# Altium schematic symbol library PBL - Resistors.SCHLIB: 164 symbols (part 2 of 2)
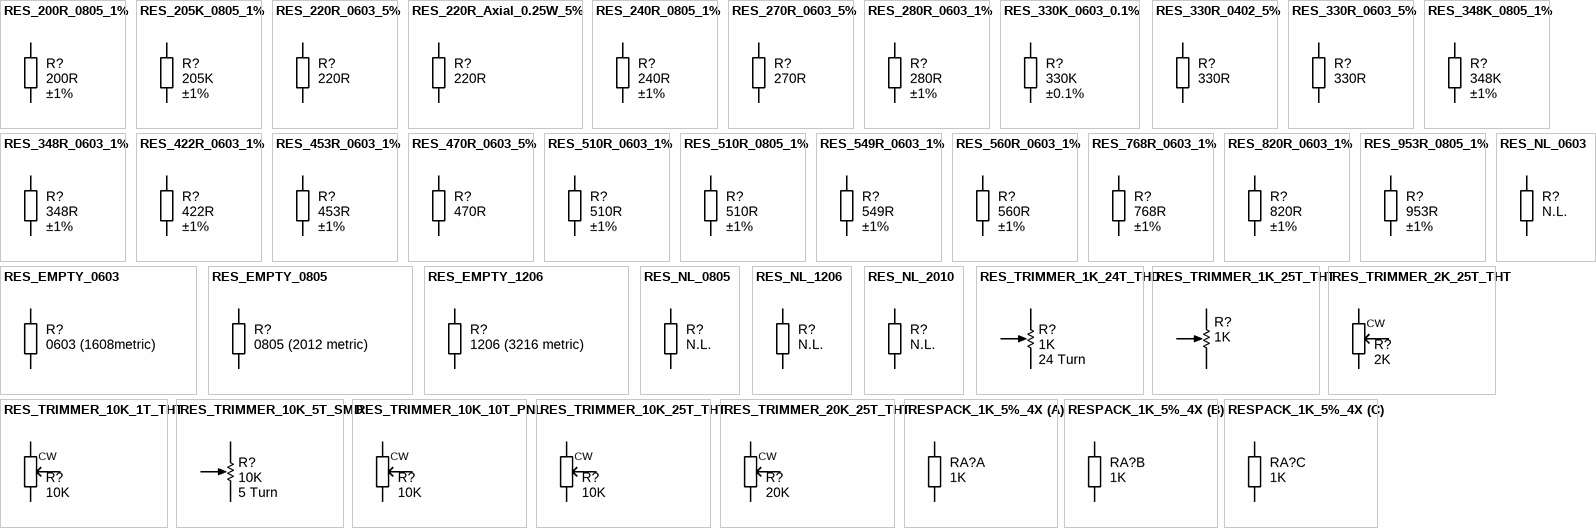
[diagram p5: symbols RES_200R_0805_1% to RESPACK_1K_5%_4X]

## RES_TRIMMER_10K_1T_THT
designator R?, comment value 10K  (hidden comment: Single-turn pot)
Trimmer THD 10K 200mW Single-turn; Manufacturer 1: Bourns Inc.; Manufacturer Part Number 1: 3306F-1-103; Tolerance: ±25%; Ratings: 1/5W; SCDType: spec
footprint POT_3306F
pins: CCW 1, CW 3, W 2

## RES_TRIMMER_10K_5T_SMD
designator R?, comment 5 Turn  value 10K
Trimmer SMD 10K 250mW 5-turn Side-adjust; Manufacturer 1: Bourns Inc.; Manufacturer Part Number 1: 3214G-1-103E; Tolerance: 10%; Ratings: 5 turn variable cermet; Number of Turns: 5; SCDType: spec
footprint TrimPot_SMD_Bourns_3214G (Bourns- 3214G - TRIMMER)
pins: 1 CCW, 2 WIPER, 3 CW

## RES_TRIMMER_10K_10T_PNL
designator R?, comment value 10K  (hidden comment: 10 turns)  (mechanical)
Trimmer panel mount 10K 2W 10-turn; Manufacturer: Bourns Inc.; Manufacturer Part Number: 3590S-2-103L; Tolerance: ±5%; Ratings: 2W; ±50ppm/°C; SCDType: spec
pins: 1 CCW, 2 W, 3 CW

## RES_TRIMMER_10K_25T_THT
designator R?, comment value 10K  (hidden comment: 25 turns)
Trimmer THD 10K 500mW 25-turn; Manufacturer 1: Murata Electronics North America; Manufacturer Part Number 1: PV36X103C01B00; Tolerance: ±10%; Ratings: 1/2W; ±100ppm/°C; SCDType: spec
footprint TRIMPOT_THT_PV36X (TRIMMER, MURATA, PV36X)
pins: CCW 1, CW 3, W 2

## RES_TRIMMER_20K_25T_THT
designator R?, comment value 20K  (hidden comment: 25 turns)
Trimmer THD 20K 500mW 25-turn; Manufacturer 1: Murata Electronics North America; Manufacturer Part Number 1: PV36X203C01B00; Tolerance: ±10%; Ratings: 1/2W; ±100ppm/°C; SCDType: spec
footprint TrimPot_THT_PV36X (TRIMMER, MURATA, PV36X)
pins: CCW 1, CW 3, W 2

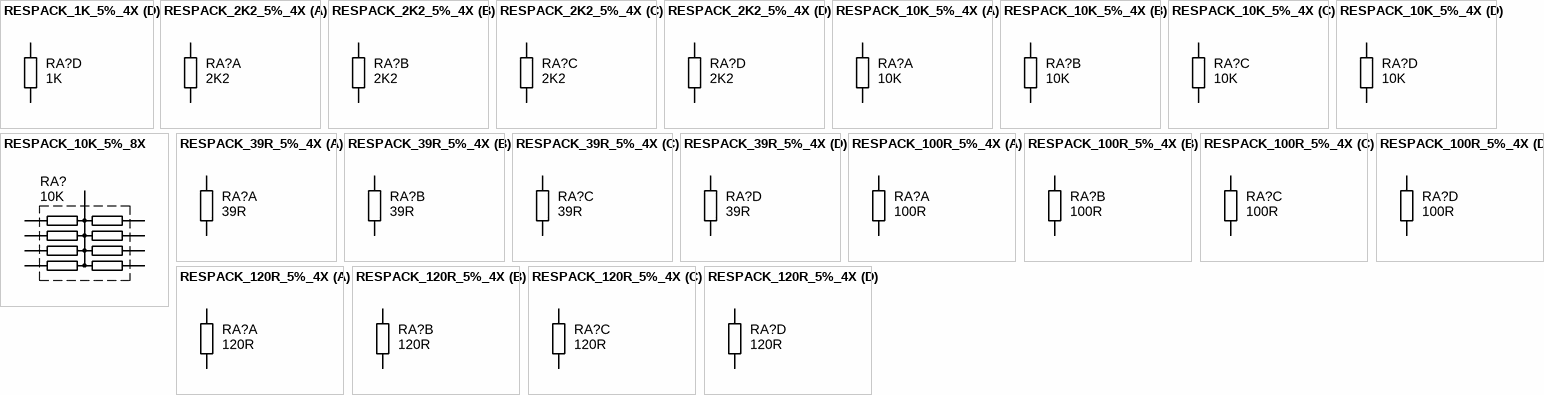
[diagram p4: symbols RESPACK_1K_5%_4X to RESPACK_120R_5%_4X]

## RESPACK_1K_5%_4X
designator RA?, comment value 1K  (hidden comment: Film Res Pack)
Resistor array 1K Ohm 4-pack 62.5mW 5% 4x1608 SMD; Manufacturer 1: Yageo; Manufacturer Part Number 1: YC164-JR-071KL; Ratings: 1/16 W; Number of Resistors: 4; Circuit Type: Isolated; SCDType: source
footprint RESCAXS50P160X320X70-8N (Resistor Pack, Body 1.6x3.2mm, 4x0603, IPC Medium Density)
part A pins: 1, 8
part B pins: 2, 7
part C pins: 3, 6
part D pins: 4, 5

## RESPACK_2K2_5%_4X
designator RA?, comment value 2K2  (hidden comment: Thick Film)
Resistor array 2.2K Ohm 4-pack 62.5mW 5% 4x1608 SMD; Manufacturer 1: Yageo; Manufacturer Part Number 1: YC164-JR-072K2L; Ratings: 1/16 W; Number of Resistors: 4; Circuit Type: Isolated; SCDType: source
footprint RESCAXS50P160X320X70-8N (Resistor Pack, Body 1.6x3.2mm, 4x0603, IPC Medium Density)
part A pins: 1, 8
part B pins: 2, 7
part C pins: 3, 6
part D pins: 4, 5

## RESPACK_10K_5%_4X
designator RA?, comment value 10K  (hidden comment: Film Res Cap)
Resistor array 10K Ohm 4-pack 62.5mW 5% 4x1608 SMD; Manufacturer 1: Yageo; Manufacturer Part Number 1: YC164-JR-0710KL; Ratings: 1/16 W; Number of Resistors: 4; Circuit Type: Isolated; SCDType: source
footprint RESCAXS50P160X320X70-8N (Resistor Pack, Body 1.6x3.2mm, 4x0603, IPC Medium Density)
part A pins: 1, 8
part B pins: 2, 7
part C pins: 3, 6
part D pins: 4, 5

## RESPACK_10K_5%_8X
designator RA?, comment value 10K  (hidden comment: Thick Film)
Resistor array 10K Ohm 8-pack 62.5mW 5% 1608 SMD; Manufacturer 1: Panasonic - ECG; Manufacturer Part Number 1: EXB-E10C103J; Ratings: 1/16 W; Number of Resistors: 8; SCDType: source
footprint RESP4021N8X (Resistor Pack, Body 4.0x2.1mm, 8 elements bussed, IPC Medium Density)
pins: 1 COM, 2, 3, 4, 5, 6 COM, 7, 8, 9, 10

## RESPACK_39R_5%_4X
designator RA?, comment value 39R  (hidden comment: Thick Film)
Resistor array 39 Ohm 4-pack 62.5mW 5% 4x1608 SMD; Manufacturer 1: Yageo; Manufacturer Part Number 1: YC164-JR-0739RL; Ratings: 1/16 W; Number of Resistors: 4; Circuit Type: Isolated; Parameter Name: ±200ppm/°C; SCDType: source
footprint RESCAXS50P160X320X70-8N (Resistor Pack, Body 1.6x3.2mm, 4x0603, IPC Medium Density)
part A pins: 1, 8
part B pins: 2, 7
part C pins: 3, 6
part D pins: 4, 5

## RESPACK_100R_5%_4X
designator RA?, comment value 100R  (hidden comment: Thick Film)
Resistor array 100 Ohm 4-pack 62.5mW 5% 4x1608 SMD; Manufacturer 1: Yageo; Manufacturer Part Number 1: YC164-JR-07100RL; Ratings: 1/16 W; Number of Resistors: 4; Circuit Type: Isolated; Parameter Name: ±200ppm/°C; SCDType: source
footprint RESCAXS50P160X320X70-8N (Resistor Pack, Body 1.6x3.2mm, 4x0603, IPC Medium Density)
part A pins: 1, 8
part B pins: 2, 7
part C pins: 3, 6
part D pins: 4, 5

## RESPACK_120R_5%_4X
designator RA?, comment value 120R  (hidden comment: Thick Film)
Resistor array 120 Ohm 4-pack 62.5mW 5% 4x1608 SMD; Manufacturer 1: Yageo; Manufacturer Part Number 1: YC164-JR-07120RL; Ratings: 1/16 W; Number of Resistors: 4; Circuit Type: Isolated; Parameter Name: ±200ppm/°C; SCDType: source
footprint RESCAXS50P160X320X70-8N (Resistor Pack, Body 1.6x3.2mm, 4x0603, IPC Medium Density)
part A pins: 1, 8
part B pins: 2, 7
part C pins: 3, 6
part D pins: 4, 5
